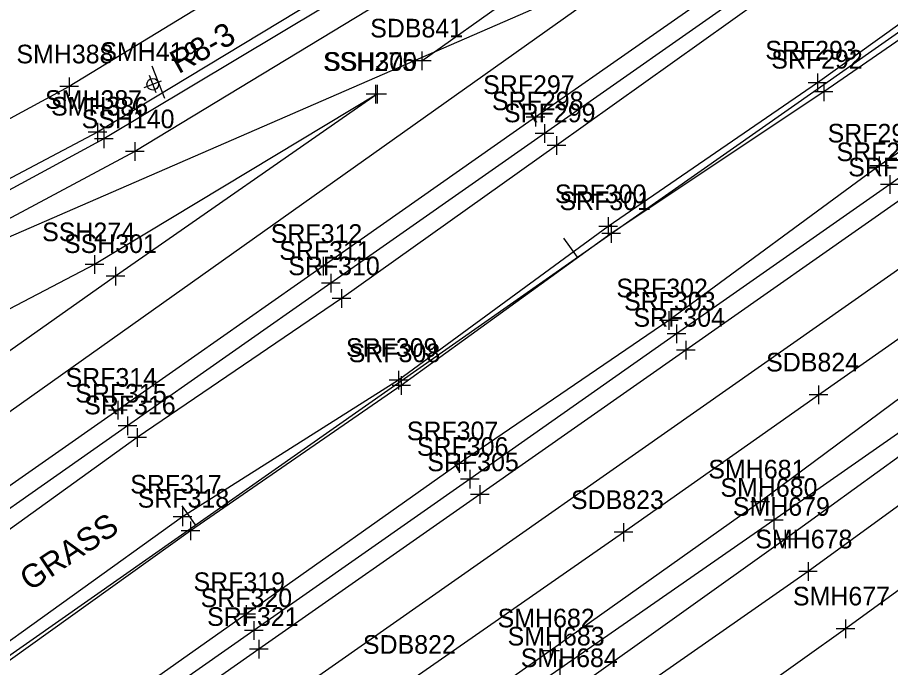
# Model space of a CAD drawing. Extents: x 941041 to 969446, y 397014 to 416764.
# Drawn here: x 952620 to 952807.2, y 403770.9 to 403910.4 of the extents above; entities that cross this region are included whole.
import ezdxf

# ---------------------------------------------------------------- set-up
doc = ezdxf.new("R2010")
doc.units = 0
for name, color, linetype in [('SURVEY - CENTERLINE - Preliminary', 7, 'Continuous'), ('SURVEY - CENTERLINE - Preliminary Curve Text', 7, 'Continuous'), ('SURVEY - DRAINAGE - Area Shapes', 7, 'Continuous'), ('SURVEY - DTM - Breaklines', 7, 'Continuous'), ('SURVEY - DTM - Breaklines - Points - Locators', 7, 'Continuous'), ('SURVEY - DTM - Breaklines - Points - Numbers', 7, 'Continuous'), ('SURVEY - TRAFFIC CONTROL - Signs - Points - Locators', 7, 'Continuous'), ('SURVEY - TRAFFIC CONTROL - Signs - Points - Numbers', 7, 'Continuous'), ('SURVEY - TRAFFIC CONTROL - Signs and Devices with Text', 7, 'Continuous'), ('SURVEY - TRANSPORTATION - Features', 7, 'Continuous'), ('SURVEY - TRANSPORTATION - Features - Points - Locators', 7, 'Continuous'), ('SURVEY - TRANSPORTATION - Features - Points - Numbers', 7, 'Continuous'), ('SURVEY - TRANSPORTATION - Roads', 7, 'Continuous'), ('SURVEY - TRANSPORTATION - Roads - Points - Locators', 7, 'Continuous'), ('SURVEY - TRANSPORTATION - Roads - Points - Numbers', 7, 'Continuous'), ('SURVEY - VEGETATION - Features with Text', 7, 'Continuous')]:
    doc.layers.add(name, color=color, linetype=linetype)

msp = doc.modelspace()

# ---------------------------------------------------------------- linework, layer by layer
at = {"layer": 'SURVEY - CENTERLINE - Preliminary'}
msp.add_line((950966.25, 402614.81), (953884.31, 404661.52), dxfattribs=at)
msp.add_line((950966.25, 402614.81), (953884.31, 404661.52), dxfattribs=at)
msp.add_line((950966.25, 402614.81), (953884.31, 404661.52), dxfattribs=at)
at = {"layer": 'SURVEY - CENTERLINE - Preliminary Curve Text'}
for p, q in [((952740.06, 403858.95), (952737.19, 403863.04)), ((952658.19, 403801.52), (952655.32, 403805.62))]:
    msp.add_line(p, q, dxfattribs=at)
at = {"layer": 'SURVEY - DRAINAGE - Area Shapes'}
for points in [[(954050.98, 404130.56), (953837.45, 404341.16), (953706.36, 404460.47), (953686.21, 404471.93), (953450.22, 404306.36), (952524.78, 403657.05)], [(951145.6, 402792.15), (951562.19, 403084.02), (952475.83, 403724.71), (952754.77, 403922.8), (952578.99, 403846.21), (952455.44, 403792), (952334.19, 403750.29), (951972.51, 403632.53), (951887.41, 403584.59)]]:
    msp.add_lwpolyline(points, dxfattribs=at)
at = {"layer": 'SURVEY - DTM - Breaklines'}
for points in [[(953407.93, 404328.96), (953362.09, 404296.51), (953318.37, 404266.14), (953270.93, 404233.01), (953226.07, 404201.97), (953175.78, 404166.42), (953127.23, 404132.58), (953078.51, 404097.88), (953032.08, 404064.83), (952981.28, 404029.12), (952933.65, 403996.05), (952884.24, 403960.77), (952839.78, 403931.02), (952791.6, 403896.4), (952746.65, 403865.57), (952701.7, 403832.59), (952655.41, 403803.24), (952607.97, 403769.21), (952563.45, 403739.45), (952518.57, 403707.51), (952485.83, 403683.52)], [(953409.35, 404326.94), (953363.72, 404294.68), (953319.81, 404264.04), (953272.32, 404230.67), (953227.42, 404200.09), (953177.07, 404164.22), (953128.05, 404130.78), (953079.51, 404095.64), (953032.98, 404063.07), (952982.65, 404027.16), (952934.62, 403994.21), (952885.08, 403959.16), (952841.29, 403927.93), (952792.89, 403894.45), (952747.31, 403864.07), (952702.31, 403831.43), (952657.06, 403800.22), (952609.82, 403766.37), (952565.08, 403736.8), (952521.93, 403702.28), (952487.22, 403681.48)], [(952926.3, 404087.24), (952879.52, 404057.61), (952830.69, 404022.3), (952779.17, 403990.28), (952731.62, 403957.52), (952677.88, 403924.22), (952631.05, 403895.57), (952585.42, 403870.88), (952537.91, 403849.33), (952504.22, 403833.31), (952461.19, 403814.66), (952421.18, 403809.04)], [(952706.71, 403901.13), (952744.58, 403928.06), (952783.83, 403955.9), (952823.99, 403983.96), (952862.24, 404010.78), (952901.26, 404038.35), (952942.44, 404066.85)], [(952447.47, 403587.87), (952492.12, 403619.04), (952535.18, 403649.21), (952579.12, 403679.85), (952622.63, 403710.51), (952664.16, 403739.7), (952705.31, 403768.85), (952749.94, 403799.92), (952791.79, 403829.44), (952831.3, 403857.21), (952872.52, 403885.88), (952913.94, 403914.99), (952957.12, 403945.2), (952999.49, 403974.88), (953016.81, 403987.05)], [(952917.54, 403887.23), (952879.05, 403856.17), (952834.15, 403824), (952789.53, 403791.48), (952743.17, 403759.1), (952699.51, 403726.33), (952652.89, 403694.34), (952605.64, 403661.7), (952558.8, 403631.47), (952496.14, 403581.58), (952474.11, 403564.31), (952441.21, 403533.58), (952397.8, 403490.51), (952380.05, 403468.98)], [(952926.5, 403873.35), (952887.88, 403844.74), (952842.1, 403811.64), (952797.54, 403779.23), (952751.48, 403746.32), (952706.83, 403715.15), (952659.98, 403683.17), (952615.08, 403648.75)]]:
    msp.add_lwpolyline(points, dxfattribs=at)
at = {"layer": 'SURVEY - DTM - Breaklines - Points - Locators'}
for p, q in [((952706.71, 403903.13), (952706.71, 403899.13)), ((952708.71, 403901.13), (952704.71, 403901.13)), ((952631.05, 403897.57), (952631.05, 403893.57)), ((952791.6, 403898.4), (952791.6, 403894.4)), ((952633.05, 403895.57), (952629.05, 403895.57)), ((952793.6, 403896.4), (952789.6, 403896.4)), ((952792.89, 403896.45), (952792.89, 403892.45)), ((952794.89, 403894.45), (952790.89, 403894.45)), ((952746.65, 403867.57), (952746.65, 403863.57)), ((952748.65, 403865.57), (952744.65, 403865.57)), ((952747.31, 403866.07), (952747.31, 403862.07)), ((952749.31, 403864.07), (952745.31, 403864.07)), ((952701.7, 403834.59), (952701.7, 403830.59)), ((952702.31, 403833.43), (952702.31, 403829.43)), ((952703.7, 403832.59), (952699.7, 403832.59)), ((952704.31, 403831.43), (952700.31, 403831.43)), ((952791.79, 403831.44), (952791.79, 403827.44)), ((952793.79, 403829.44), (952789.79, 403829.44)), ((952655.41, 403805.24), (952655.41, 403801.24)), ((952657.41, 403803.24), (952653.41, 403803.24)), ((952657.06, 403802.22), (952657.06, 403798.22)), ((952749.94, 403801.92), (952749.94, 403797.92)), ((952659.06, 403800.22), (952655.06, 403800.22)), ((952751.94, 403799.92), (952747.94, 403799.92)), ((952789.53, 403793.48), (952789.53, 403789.48)), ((952791.53, 403791.48), (952787.53, 403791.48)), ((952797.54, 403781.23), (952797.54, 403777.23)), ((952799.54, 403779.23), (952795.54, 403779.23))]:
    msp.add_line(p, q, dxfattribs=at)
at = {"layer": 'SURVEY - TRAFFIC CONTROL - Signs - Points - Locators'}
for p, q in [((952649.75, 403894.25), (952648.28, 403897.97)), ((952647.15, 403895.38), (952650.87, 403896.85))]:
    msp.add_line(p, q, dxfattribs=at)
at = {"layer": 'SURVEY - TRAFFIC CONTROL - Signs and Devices with Text'}
msp.add_line((952648.78, 403900.05), (952651.53, 403893.07), dxfattribs=at)
msp.add_circle((952649, 403896.08), 1.25, dxfattribs=at)
at = {"layer": 'SURVEY - TRANSPORTATION - Features'}
for points in [[(952933.14, 404076.27), (952887.45, 404046.15), (952837.64, 404013.54), (952785.68, 403979.98), (952738.91, 403948.87), (952684.07, 403914.13), (952637.14, 403885.81), (952590.48, 403861.12), (952543.25, 403838.13), (952509.28, 403823.74), (952464.01, 403805.95), (952423.37, 403791.98), (952398.44, 403784.2)], [(952970.12, 404047.84), (952922.32, 404014.23), (952874.43, 403979.59), (952827.68, 403948.11), (952779.12, 403914), (952735.58, 403882.93), (952689.47, 403850.1), (952645.64, 403820.24), (952597.37, 403785.52)], [(953044.12, 404045.63), (952994.26, 404010.63), (952946.21, 403976.34), (952896.87, 403942.61), (952851.11, 403910.43), (952804.81, 403878.59), (952759.67, 403845.36), (952714.73, 403814.69), (952669, 403782.32), (952622.56, 403749.53), (952577.8, 403717.92)], [(952913.84, 403893.14), (952874.52, 403863.56), (952829.06, 403830.64), (952784.66, 403798.47), (952739.16, 403766), (952693.74, 403734.13), (952648.44, 403702.25), (952600.48, 403670.02), (952552.63, 403637.1), (952490.83, 403589.2), (952470.74, 403572.76), (952463.7, 403566.84)]]:
    msp.add_lwpolyline(points, dxfattribs=at)
at = {"layer": 'SURVEY - TRANSPORTATION - Features - Points - Locators'}
for p, q in [((952637.14, 403887.81), (952637.14, 403883.81)), ((952639.14, 403885.81), (952635.14, 403885.81)), ((952735.58, 403884.93), (952735.58, 403880.93)), ((952737.58, 403882.93), (952733.58, 403882.93)), ((952804.81, 403880.59), (952804.81, 403876.59)), ((952806.81, 403878.59), (952802.81, 403878.59)), ((952689.47, 403852.1), (952689.47, 403848.1)), ((952691.47, 403850.1), (952687.47, 403850.1)), ((952759.67, 403847.36), (952759.67, 403843.36)), ((952761.67, 403845.36), (952757.67, 403845.36)), ((952645.64, 403822.24), (952645.64, 403818.24)), ((952647.64, 403820.24), (952643.64, 403820.24)), ((952714.73, 403816.69), (952714.73, 403812.69)), ((952716.73, 403814.69), (952712.73, 403814.69)), ((952784.66, 403800.47), (952784.66, 403796.47)), ((952786.66, 403798.47), (952782.66, 403798.47)), ((952669, 403784.32), (952669, 403780.32)), ((952671, 403782.32), (952667, 403782.32))]:
    msp.add_line(p, q, dxfattribs=at)
at = {"layer": 'SURVEY - TRANSPORTATION - Roads'}
for points in [[(953854.31, 404705.09), (953803.66, 404669.9), (953752.1, 404633.3), (953704.99, 404600.66), (953647.26, 404560.28), (953593.35, 404522.18), (953538.64, 404483.8), (953481.57, 404443.82), (953428.95, 404406.84), (953375.39, 404369.37), (953319.63, 404330.36), (953264.54, 404291.54), (953207.01, 404251.04), (953151.83, 404212.71), (953097.91, 404174.93), (953044.02, 404137.15), (952991.3, 404100.41), (952936.63, 404064.07), (952879.17, 404027.52), (952819.51, 403989.75), (952762.74, 403954.2), (952705, 403918.02), (952645.15, 403881.65), (952578.99, 403846.21)], [(952934.03, 404074.71), (952888.55, 404044.62), (952838.51, 404012.17), (952786.91, 403978.67), (952739.91, 403946.98), (952685.69, 403912.66), (952638.54, 403884.36), (952591.73, 403859.06), (952544.12, 403835.44), (952510.28, 403819.86), (952465.64, 403801.52), (952423.67, 403785.82), (952400.69, 403777.65)], [(952966.99, 404054.39), (952917.91, 404020.1), (952869.96, 403986.54), (952824.01, 403954.19), (952777.01, 403921.15), (952731.1, 403889), (952685.55, 403857.05), (952641.53, 403826.17), (952594.17, 403793.02)], [(952968.52, 404050.78), (952920.2, 404016.82), (952872.23, 403982.99), (952826.18, 403950.85), (952778.11, 403917.2), (952733.04, 403885.52), (952687.21, 403853.4), (952643.61, 403822.77), (952594.67, 403788.44)], [(953046.11, 404041.98), (952997.22, 404007.75), (952947.55, 403972.95), (952899.56, 403939.37), (952853.51, 403907.24), (952807.05, 403874.59), (952761.33, 403842.53), (952717, 403811.35), (952670.69, 403778.86), (952625.22, 403746.95), (952579.91, 403715.1)], [(953047.38, 404038.13), (952999.67, 404004.66), (952947.65, 403968.16), (952902.02, 403936.14), (952856.05, 403904.05), (952809.41, 403871.32), (952763.34, 403839.04), (952719.12, 403808.03), (952671.74, 403774.84), (952627.47, 403743.75), (952581.75, 403711.66)], [(952905.89, 403902.49), (952867.28, 403872.76), (952823.67, 403839.47), (952779.24, 403806.48), (952734.21, 403774.52), (952688.26, 403742.16), (952642.64, 403710.46), (952595.33, 403677.1), (952547.64, 403643.77), (952484.32, 403598.74), (952462.03, 403582.12), (952455.35, 403576.86)], [(952912.48, 403895.47), (952872.63, 403866.2), (952826.96, 403833.82), (952782.17, 403802.55), (952736.34, 403770.63), (952690.18, 403738.66), (952644.94, 403707.09), (952597.62, 403673.8), (952550.6, 403640.2), (952487.73, 403593.63), (952466.12, 403577.04), (952459.67, 403571.86)], [(952697.16, 403893.97), (952636.52, 403857.4), (952587.51, 403831.79), (952534.88, 403806.99), (952483.18, 403785.72), (952429.44, 403765.14), (952375.1, 403746.86), (952316.97, 403727.68), (952269.24, 403712.39), (952214.85, 403694.47), (952162.76, 403677.58), (952105.34, 403658.92), (952051.28, 403641.38), (951999.19, 403624.43), (951950.5, 403607.88), (951929.86, 403596.04), (951918.46, 403586), (951908.99, 403572.79), (951900.68, 403550.6), (951895.43, 403527.92)], [(952697.16, 403893.97), (952641.04, 403854.87), (952584.14, 403814.78), (952532.55, 403778.68), (952481.32, 403742.62), (952431.11, 403707.16), (952375.85, 403668.53), (952325.36, 403633.08), (952273.9, 403596.95), (952221.23, 403559.82), (952172.53, 403526.04), (952120.87, 403489.74), (952069.02, 403453.35), (952013.3, 403414.51)]]:
    msp.add_lwpolyline(points, dxfattribs=at)
at = {"layer": 'SURVEY - TRANSPORTATION - Roads - Points - Locators'}
for p, q in [((952696.77, 403895.96), (952696.77, 403891.96)), ((952697.16, 403895.97), (952697.16, 403891.97)), ((952698.77, 403893.96), (952694.77, 403893.96)), ((952699.16, 403893.97), (952695.16, 403893.97)), ((952731.1, 403891), (952731.1, 403887)), ((952733.1, 403889), (952729.1, 403889)), ((952638.54, 403886.36), (952638.54, 403882.36)), ((952733.04, 403887.52), (952733.04, 403883.52)), ((952640.54, 403884.36), (952636.54, 403884.36)), ((952735.04, 403885.52), (952731.04, 403885.52)), ((952645.15, 403883.65), (952645.15, 403879.65)), ((952647.15, 403881.65), (952643.15, 403881.65)), ((952807.05, 403876.59), (952807.05, 403872.59)), ((952809.05, 403874.59), (952805.05, 403874.59)), ((952636.52, 403859.4), (952636.52, 403855.4)), ((952685.55, 403859.05), (952685.55, 403855.05)), ((952638.52, 403857.4), (952634.52, 403857.4)), ((952641.04, 403856.87), (952641.04, 403852.87)), ((952687.55, 403857.05), (952683.55, 403857.05)), ((952643.04, 403854.87), (952639.04, 403854.87)), ((952687.21, 403855.4), (952687.21, 403851.4)), ((952689.21, 403853.4), (952685.21, 403853.4)), ((952761.33, 403844.53), (952761.33, 403840.53)), ((952763.33, 403842.53), (952759.33, 403842.53)), ((952763.34, 403841.04), (952763.34, 403837.04)), ((952765.34, 403839.04), (952761.34, 403839.04)), ((952641.53, 403828.17), (952641.53, 403824.17)), ((952643.53, 403826.17), (952639.53, 403826.17)), ((952643.61, 403824.77), (952643.61, 403820.77)), ((952645.61, 403822.77), (952641.61, 403822.77)), ((952717, 403813.35), (952717, 403809.35)), ((952719, 403811.35), (952715, 403811.35)), ((952719.12, 403810.03), (952719.12, 403806.03)), ((952721.12, 403808.03), (952717.12, 403808.03)), ((952779.24, 403808.48), (952779.24, 403804.48)), ((952781.24, 403806.48), (952777.24, 403806.48)), ((952782.17, 403804.55), (952782.17, 403800.55)), ((952784.17, 403802.55), (952780.17, 403802.55)), ((952670.69, 403780.86), (952670.69, 403776.86)), ((952672.69, 403778.86), (952668.69, 403778.86)), ((952671.74, 403776.84), (952671.74, 403772.84)), ((952734.21, 403776.52), (952734.21, 403772.52)), ((952673.74, 403774.84), (952669.74, 403774.84)), ((952736.21, 403774.52), (952732.21, 403774.52)), ((952736.34, 403772.63), (952736.34, 403768.63))]:
    msp.add_line(p, q, dxfattribs=at)

# ---------------------------------------------------------------- texts
at = {"layer": 'SURVEY - DTM - Breaklines - Points - Numbers'}
for s, p in [('SDB841', (952695.63, 403906.13)), ('SMH388', (952619.76, 403900.57)), ('SRF293', (952780.36, 403901.4)), ('SRF292', (952781.65, 403899.45)), ('SRF300', (952735.24, 403870.57)), ('SRF301', (952736.23, 403869.07)), ('SRF309', (952690.44, 403837.59)), ('SRF308', (952691.02, 403836.43)), ('SDB824', (952780.55, 403834.44)), ('SRF317', (952644.17, 403808.24)), ('SRF318', (952645.77, 403805.22)), ('SDB823', (952738.7, 403804.92)), ('SMH678', (952778.24, 403796.48)), ('SMH677', (952786.3, 403784.23)), ('SDB822', (952694.07, 403773.85))]:
    msp.add_text(s, height=4, dxfattribs=at).set_placement(p)
at = {"layer": 'SURVEY - TRAFFIC CONTROL - Signs - Points - Numbers'}
msp.add_text('SMH419', height=4, dxfattribs=at).set_placement((952637.76, 403901.11))
at = {"layer": 'SURVEY - TRAFFIC CONTROL - Signs and Devices with Text'}
msp.add_text('R8-3', height=5, rotation=29.1927, dxfattribs=at).set_placement((952654.53, 403898.22))
at = {"layer": 'SURVEY - TRANSPORTATION - Features - Points - Numbers'}
for s, p in [('SMH387', (952625.9, 403890.81)), ('SRF299', (952724.33, 403887.93)), ('SRF291', (952793.73, 403883.59)), ('SRF310', (952678.06, 403855.1)), ('SRF302', (952748.43, 403850.36)), ('SRF316', (952634.29, 403825.24)), ('SRF307', (952703.49, 403819.69)), ('SMH679', (952773.41, 403803.47)), ('SRF319', (952657.74, 403787.32)), ('SMH684', (952727.92, 403771))]:
    msp.add_text(s, height=4, dxfattribs=at).set_placement(p)
at = {"layer": 'SURVEY - TRANSPORTATION - Roads - Points - Numbers'}
for s, p in [('SSH275', (952685.53, 403898.96)), ('SSH300', (952685.75, 403898.97)), ('SRF297', (952719.86, 403894)), ('SMH386', (952627.19, 403889.36)), ('SRF298', (952721.75, 403890.52)), ('SSH140', (952633.74, 403886.65)), ('SRF290', (952795.64, 403879.59)), ('SRF289', (952798.16, 403876.32)), ('SSH274', (952625.28, 403862.4)), ('SRF312', (952674.31, 403862.05)), ('SSH301', (952629.96, 403859.87)), ('SRF311', (952676.13, 403858.4)), ('SRF303', (952750.09, 403847.53)), ('SRF304', (952752.1, 403844.04)), ('SRF314', (952630.29, 403831.17)), ('SRF315', (952632.37, 403827.77)), ('SRF306', (952705.65, 403816.35)), ('SRF305', (952707.88, 403813.03)), ('SMH681', (952768.16, 403811.48)), ('SMH680', (952770.75, 403807.55)), ('SRF320', (952659.27, 403783.86)), ('SRF321', (952660.66, 403779.84)), ('SMH682', (952722.97, 403779.52)), ('SMH683', (952725.1, 403775.63))]:
    msp.add_text(s, height=4, dxfattribs=at).set_placement(p)
at = {"layer": 'SURVEY - VEGETATION - Features with Text'}
msp.add_text('GRASS', height=4.998, rotation=33.7585, dxfattribs=at).set_placement((952622.66, 403787.18))

doc.saveas('drawing.dxf')
